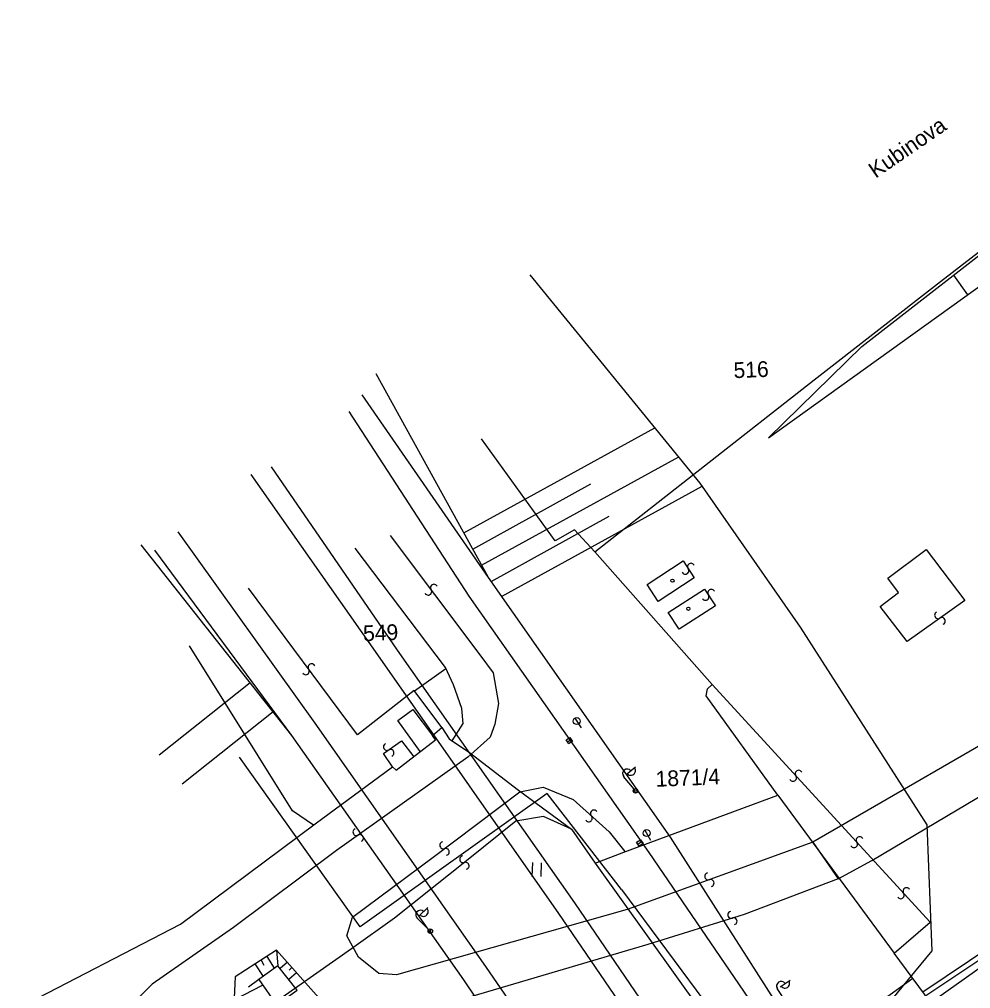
# Model space of a CAD drawing. Extents: x -469926 to -462499, y -1098642 to -1092733.
# Drawn here: x -469799.5 to -469696.9, y -1098386.8 to -1098282.2 of the extents above; entities that cross this region are included whole.
import ezdxf

# ---------------------------------------------------------------- set-up
doc = ezdxf.new("R2010")
doc.units = 0
for name, color, linetype in [('Vrstva 1', 7, 'Continuous'), ('Vrstva 10', 7, 'Continuous'), ('Vrstva 12', 7, 'Continuous'), ('Vrstva 13', 7, 'Continuous'), ('Vrstva 14', 7, 'Continuous'), ('Vrstva 16', 7, 'Continuous'), ('Vrstva 26', 7, 'Continuous'), ('Vrstva 48', 7, 'Continuous'), ('Vrstva 50', 7, 'Continuous'), ('Vrstva 51', 7, 'Continuous'), ('Vrstva 6', 7, 'Continuous'), ('Vrstva 62', 7, 'Continuous'), ('Vrstva 8', 7, 'Continuous')]:
    doc.layers.add(name, color=color, linetype=linetype)

msp = doc.modelspace()

# ---------------------------------------------------------------- linework, layer by layer
at = {"layer": 'Vrstva 1'}
for p, q in [((-469741.67, -1098338.48), (-469749.64, -1098327.48)), ((-469739.61, -1098337.27), (-469741.67, -1098338.48)), ((-469737.41, -1098339.64), (-469739.61, -1098337.27)), ((-469759.48, -1098337.88), (-469749.9, -1098350.61)), ((-469753.52, -1098352.14), (-469763.27, -1098339.25)), ((-469705.77, -1098342.49), (-469701.66, -1098339.41)), ((-469701.66, -1098339.41), (-469697.47, -1098344.89)), ((-469731.76, -1098343.19), (-469727.88, -1098340.64)), ((-469727.88, -1098340.64), (-469726.69, -1098342.46)), ((-469726.69, -1098342.46), (-469730.57, -1098345.01)), ((-469704.65, -1098344.03), (-469705.77, -1098342.49)), ((-469763.01, -1098359.39), (-469774.77, -1098343.59)), ((-469730.57, -1098345.01), (-469731.76, -1098343.19)), ((-469729.47, -1098346.21), (-469725.55, -1098343.68)), ((-469725.55, -1098343.68), (-469724.39, -1098345.48)), ((-469706.62, -1098345.57), (-469704.65, -1098344.03)), ((-469724.39, -1098345.48), (-469728.3, -1098348.01)), ((-469703.71, -1098349.34), (-469706.62, -1098345.57)), ((-469697.47, -1098344.89), (-469703.71, -1098349.34)), ((-469728.3, -1098348.01), (-469729.47, -1098346.21)), ((-469770.01, -1098367.6), (-469781.13, -1098349.79)), ((-469749.9, -1098350.61), (-469748.37, -1098352.7)), ((-469753.46, -1098352.28), (-469756.85, -1098354.69)), ((-469752.64, -1098353.99), (-469753.52, -1098352.14)), ((-469748.37, -1098352.7), (-469747.8, -1098356.01)), ((-469751.75, -1098356.57), (-469752.64, -1098353.99)), ((-469701.21, -1098379.6), (-469724.73, -1098353.98)), ((-469756.89, -1098354.63), (-469763.01, -1098359.39)), ((-469753.89, -1098358.61), (-469756.89, -1098354.63)), ((-469747.8, -1098356.01), (-469748.2, -1098358.26)), ((-469758.66, -1098357.86), (-469757.05, -1098356.65)), ((-469757.05, -1098356.65), (-469754.9, -1098359.45)), ((-469751.59, -1098358.18), (-469751.75, -1098356.57)), ((-469756.23, -1098361.2), (-469758.66, -1098357.86)), ((-469752.79, -1098360.03), (-469751.59, -1098358.18)), ((-469748.2, -1098358.26), (-469748.69, -1098359.63)), ((-469760.19, -1098361.4), (-469758.26, -1098360.03)), ((-469758.26, -1098360.03), (-469756.94, -1098361.76)), ((-469748.69, -1098359.63), (-469751.1, -1098361.81)), ((-469759.22, -1098362.85), (-469760.19, -1098361.4)), ((-469751.1, -1098361.81), (-469765.28, -1098371.88)), ((-469754.83, -1098372.57), (-469745.5, -1098365.55)), ((-469745.5, -1098365.55), (-469742.99, -1098365.02)), ((-469742.99, -1098365.02), (-469739.74, -1098366.38)), ((-469739.74, -1098366.38), (-469735.86, -1098369.84)), ((-469717.67, -1098365.91), (-469705.09, -1098382.95)), ((-469767.75, -1098369.14), (-469770.01, -1098367.6)), ((-469745.94, -1098368.71), (-469751.24, -1098372.98)), ((-469742.94, -1098368.19), (-469745.94, -1098368.71)), ((-469739.93, -1098369.57), (-469742.94, -1098368.19)), ((-469735.86, -1098369.84), (-469734.16, -1098371.99)), ((-469765.28, -1098371.88), (-469776.4, -1098380.18)), ((-469713.88, -1098370.96), (-469733.91, -1098378.24)), ((-469763.53, -1098379.07), (-469754.83, -1098372.57)), ((-469751.24, -1098372.98), (-469759.03, -1098379.15)), ((-469737.37, -1098373.25), (-469719.43, -1098398.24)), ((-469711.13, -1098374.94), (-469721.29, -1098378.76)), ((-469702.02, -1098387.1), (-469684.12, -1098375.14)), ((-469733.91, -1098378.24), (-469758.81, -1098385.26)), ((-469764.16, -1098381.06), (-469763.53, -1098379.07)), ((-469759.03, -1098379.15), (-469763.65, -1098382.48)), ((-469721.29, -1098378.76), (-469731.67, -1098382.01)), ((-469776.4, -1098380.18), (-469785.15, -1098386.27)), ((-469705.09, -1098382.95), (-469701.21, -1098379.6)), ((-469690.82, -1098380.29), (-469701.69, -1098387.55)), ((-469762.9, -1098383.37), (-469764.16, -1098381.06)), ((-469731.67, -1098382.01), (-469759.44, -1098390.18)), ((-469763.65, -1098382.48), (-469785.81, -1098397.95)), ((-469760.7, -1098385.15), (-469762.9, -1098383.37)), ((-469677.86, -1098419.76), (-469705.09, -1098382.95)), ((-469758.81, -1098385.26), (-469760.7, -1098385.15)), ((-469785.15, -1098386.27), (-469794.77, -1098395.81)), ((-469719.86, -1098397.64), (-469703.1, -1098385.64))]:
    msp.add_line(p, q, dxfattribs=at)
at = {"layer": 'Vrstva 10'}
for points in [[(-469799.49, -1098388.81), (-469782.12, -1098379.8), (-469767.58, -1098369.01), (-469759.22, -1098362.85), (-469758.83, -1098363.21), (-469754.6, -1098359.95), (-469754.9, -1098359.45), (-469753.89, -1098358.61), (-469753.1, -1098359.82), (-469750.92, -1098361.29), (-469745.62, -1098365.35), (-469739.93, -1098369.57), (-469737.37, -1098373.25), (-469734.26, -1098372.03), (-469717.67, -1098365.91), (-469725.4, -1098355.18), (-469725.24, -1098354.43), (-469724.73, -1098353.98), (-469737.41, -1098339.64), (-469713.75, -1098321.1), (-469700.11, -1098310.5), (-469687.33, -1098300.64)], [(-469688.87, -1098356.53), (-469713.88, -1098370.96), (-469711.13, -1098374.94), (-469707.51, -1098372.93), (-469689.28, -1098362.13)]]:
    msp.add_lwpolyline(points, dxfattribs=at)
at = {"layer": 'Vrstva 12'}
for p, q in [((-469744.14, -1098373.16), (-469744.18, -1098374.66)), ((-469743.18, -1098374.69), (-469743.14, -1098373.19))]:
    msp.add_line(p, q, dxfattribs=at)
at = {"layer": 'Vrstva 13'}
for points in [[(-469763.96, -1098324.54), (-469751, -1098344.44), (-469731.57, -1098372.1), (-469716.71, -1098393.85), (-469692.47, -1098431.57), (-469671.43, -1098466.58)], [(-469772.31, -1098330.49), (-469758.73, -1098350.27), (-469739.61, -1098377.52), (-469724.95, -1098398.98), (-469700.59, -1098436.81), (-469690.24, -1098454.02), (-469679.97, -1098472.12), (-469672.53, -1098488.18)], [(-469774.52, -1098331.32), (-469760.61, -1098351.11), (-469741.31, -1098378.65), (-469726.81, -1098399.88), (-469702.02, -1098438.38), (-469691.99, -1098454.92), (-469681.79, -1098472.85), (-469672.53, -1098488.18)], [(-469782.4, -1098337.5), (-469767.61, -1098358.12), (-469749.2, -1098384.38), (-469734.61, -1098405.62), (-469710.22, -1098443.58), (-469700.74, -1098459.7), (-469691.23, -1098477.74), (-469676.77, -1098507.22), (-469668.21, -1098525.39)]]:
    msp.add_lwpolyline(points, dxfattribs=at)
at = {"layer": 'Vrstva 14'}
for centre in [(-469729.03, -1098342.77), (-469727.31, -1098345.8)]:
    msp.add_circle(centre, 0.175, dxfattribs=at)
at = {"layer": 'Vrstva 16'}
for p, q in [((-469739.55, -1098357.59), (-469738.89, -1098358.65)), ((-469740.15, -1098360.02), (-469740.15, -1098360.02)), ((-469732.01, -1098369.67), (-469731.38, -1098370.74)), ((-469732.55, -1098371.05), (-469732.55, -1098371.05))]:
    msp.add_line(p, q, dxfattribs=at)
for points in [[(-469740.36, -1098360.16), (-469740.5, -1098359.95), (-469740.08, -1098359.68), (-469739.81, -1098360.1), (-469740.23, -1098360.37), (-469740.36, -1098360.16), (-469739.94, -1098359.89)], [(-469732.76, -1098371.19), (-469732.9, -1098370.98), (-469732.49, -1098370.7), (-469732.2, -1098371.11), (-469732.62, -1098371.4), (-469732.76, -1098371.19), (-469732.35, -1098370.91)]]:
    msp.add_lwpolyline(points, dxfattribs=at)
for centre in [(-469739.35, -1098357.91), (-469731.82, -1098369.99)]:
    msp.add_circle(centre, 0.375, dxfattribs=at)
at = {"layer": 'Vrstva 26'}
for p, q in [((-469734.02, -1098363.67), (-469733.02, -1098362.84)), ((-469733.17, -1098365.24), (-469734.29, -1098363.9)), ((-469733.14, -1098365.64), (-469733.1, -1098365.2)), ((-469732.96, -1098365.68), (-469732.92, -1098365.2)), ((-469756.34, -1098378.93), (-469755.43, -1098378)), ((-469755.33, -1098380.4), (-469756.58, -1098379.18)), ((-469755.08, -1098380.81), (-469755.08, -1098380.33)), ((-469755.27, -1098380.8), (-469755.27, -1098380.36))]:
    msp.add_line(p, q, dxfattribs=at)
for centre in [(-469733.01, -1098365.43), (-469733.01, -1098365.43), (-469755.15, -1098380.57), (-469755.15, -1098380.57)]:
    msp.add_circle(centre, 0.25, dxfattribs=at)
for centre, start, end in [((-469733.9, -1098363.58), 39.781, 219.781), ((-469733.51, -1098363.26), 219.0784, 40.4836), ((-469755.88, -1098378.47), 225.0039, 46.409), ((-469756.23, -1098378.82), 45.7064, 225.7064)]:
    msp.add_arc(centre, 0.5, start, end, dxfattribs=at)
at = {"layer": 'Vrstva 48'}
for p, q in [((-469697.16, -1098311.93), (-469698.68, -1098309.81)), ((-469751.54, -1098337.61), (-469730.92, -1098326.27)), ((-469749.61, -1098341.11), (-469728.35, -1098329.42)), ((-469750.58, -1098339.36), (-469737.82, -1098332.34)), ((-469747.46, -1098344.47), (-469725.82, -1098332.57)), ((-469748.6, -1098342.84), (-469735.85, -1098335.82))]:
    msp.add_line(p, q, dxfattribs=at)
at = {"layer": 'Vrstva 50'}
msp.add_line((-469691.74, -1098381.61), (-469750.93, -1098423.51), dxfattribs=at)
at = {"layer": 'Vrstva 51'}
for centre, radius, start, end in [((-469727.64, -1098341.69), 0.376, 208.0204, 34.3315), ((-469727.02, -1098341.27), 0.377, 27.3443, 215.0075), ((-469755.38, -1098343.95), 0.376, 207.2504, 33.5615), ((-469754.76, -1098343.53), 0.377, 26.5743, 214.2375), ((-469724.84, -1098344.08), 0.377, 27.3443, 215.0075), ((-469725.46, -1098344.51), 0.376, 208.0204, 34.3315), ((-469700.36, -1098346.49), 0.376, 115.6004, 301.9115), ((-469699.96, -1098347.12), 0.377, 294.9243, 122.5875), ((-469767.96, -1098352.11), 0.377, 26.5743, 214.2375), ((-469768.58, -1098352.53), 0.376, 207.2504, 33.5615), ((-469759.83, -1098360.69), 0.376, 113.9904, 300.3015), ((-469759.45, -1098361.34), 0.377, 293.3143, 120.9775), ((-469715.4, -1098363.59), 0.377, 27.3443, 215.0075), ((-469716.02, -1098364.02), 0.376, 208.0204, 34.3315), ((-469737.5, -1098367.88), 0.377, 35.2343, 222.8975), ((-469738.05, -1098368.39), 0.376, 215.9104, 42.2215), ((-469763.12, -1098369.89), 0.376, 113.9904, 300.3015), ((-469762.74, -1098370.53), 0.377, 293.3143, 120.9775), ((-469708.82, -1098370.76), 0.377, 27.3443, 215.0075), ((-469753.75, -1098371.31), 0.376, 103.5904, 289.9015), ((-469753.49, -1098372.02), 0.377, 282.9143, 110.5775), ((-469709.44, -1098371.18), 0.376, 208.0204, 34.3315), ((-469751.6, -1098372.81), 0.376, 103.5904, 289.9015), ((-469751.34, -1098373.52), 0.377, 282.9143, 110.5775), ((-469725.17, -1098374.66), 0.376, 103.5904, 289.9015), ((-469724.91, -1098375.37), 0.377, 282.9143, 110.5775), ((-469703.77, -1098376.26), 0.377, 27.3443, 215.0075), ((-469704.39, -1098376.69), 0.376, 208.0204, 34.3315), ((-469722.69, -1098378.8), 0.376, 103.5904, 289.9015), ((-469722.43, -1098379.5), 0.377, 282.9143, 110.5775)]:
    msp.add_arc(centre, radius, start, end, dxfattribs=at)
at = {"layer": 'Vrstva 6'}
for p, q in [((-469717.42, -1098386.56), (-469716.34, -1098385.84)), ((-469716.74, -1098388.21), (-469717.71, -1098386.76))]:
    msp.add_line(p, q, dxfattribs=at)
for points in [[(-469715.05, -1098392.61), (-469729.23, -1098370.42), (-469748.89, -1098342.43), (-469762.52, -1098322.74)], [(-469736.89, -1098407.21), (-469739.06, -1098404.46), (-469739.35, -1098403.94), (-469751.54, -1098385.81), (-469770.09, -1098359.48), (-469784.89, -1098339.48)]]:
    msp.add_lwpolyline(points, dxfattribs=at)
for centre, start, end in [((-469717.29, -1098386.48), 33.8115, 213.8115), ((-469716.88, -1098386.21), 213.1089, 34.514)]:
    msp.add_arc(centre, 0.5, start, end, dxfattribs=at)
at = {"layer": 'Vrstva 62'}
for p, q in [((-469774.59, -1098353.8), (-469784.41, -1098361.57)), ((-469772.1, -1098356.93), (-469781.92, -1098364.71)), ((-469772.8, -1098383.3), (-469772.01, -1098384.57)), ((-469771.73, -1098382.6), (-469771.61, -1098384.3)), ((-469774.09, -1098384.09), (-469773.19, -1098385.44)), ((-469773.41, -1098383.69), (-469773.13, -1098384.22)), ((-469770.57, -1098383.91), (-469771.35, -1098384.61)), ((-469770.09, -1098384.48), (-469770.39, -1098384.79)), ((-469769.6, -1098385.05), (-469770.41, -1098385.77)), ((-469776.23, -1098387.92), (-469773.24, -1098386.39)), ((-469773.66, -1098385.78), (-469771.74, -1098388.52))]:
    msp.add_line(p, q, dxfattribs=at)
for points in [[(-469718.66, -1098327.37), (-469708.58, -1098317.52), (-469691.3, -1098304.07), (-469662.62, -1098282.23), (-469677.64, -1098295.01), (-469680.04, -1098299.32), (-469655.2, -1098332.03), (-469657.72, -1098331.44)], [(-469718.66, -1098327.37), (-469680.76, -1098300.16), (-469673.07, -1098311.27), (-469657.72, -1098331.44)], [(-469715.05, -1098392.61), (-469711.2, -1098393.61), (-469705.41, -1098388.06), (-469701.01, -1098382.69), (-469701.54, -1098369.1), (-469715.2, -1098347.78), (-469726.05, -1098332.25), (-469744.36, -1098309.79)], [(-469715.05, -1098392.61), (-469729.23, -1098370.42), (-469748.89, -1098342.43), (-469760.98, -1098320.45)], [(-469739.35, -1098403.94), (-469751.54, -1098385.81), (-469770.09, -1098359.48), (-469786.36, -1098338.92)], [(-469774.11, -1098392.08), (-469771.47, -1098391.58), (-469767.19, -1098387.76), (-469771.73, -1098382.6), (-469776.2, -1098385.48), (-469776.32, -1098387.75)], [(-469772.65, -1098389.16), (-469769.5, -1098386.93), (-469771.61, -1098384.3), (-469773.66, -1098385.78), (-469774.77, -1098386.59)]]:
    msp.add_lwpolyline(points, dxfattribs=at)
at = {"layer": 'Vrstva 8'}
for p, q in [((-469762.72, -1098380.1), (-469775.75, -1098361.81)), ((-469742.53, -1098365.73), (-469762.72, -1098380.1)), ((-469734.51, -1098376.08), (-469742.53, -1098365.73)), ((-469734.51, -1098376.08), (-469689.78, -1098436.28))]:
    msp.add_line(p, q, dxfattribs=at)

# ---------------------------------------------------------------- texts
at = {"layer": 'Vrstva 50'}
for s, rotation, p in [('Kubinova', 34.51, (-469707.11, -1098299.42)), ('516', 2.25, (-469722.4, -1098320.93)), ('549', 2.25, (-469762.37, -1098349.3)), ('1871/4', 2.25, (-469730.81, -1098365))]:
    msp.add_text(s, height=1.7, rotation=rotation, dxfattribs=at).set_placement(p)

doc.saveas('drawing.dxf')
